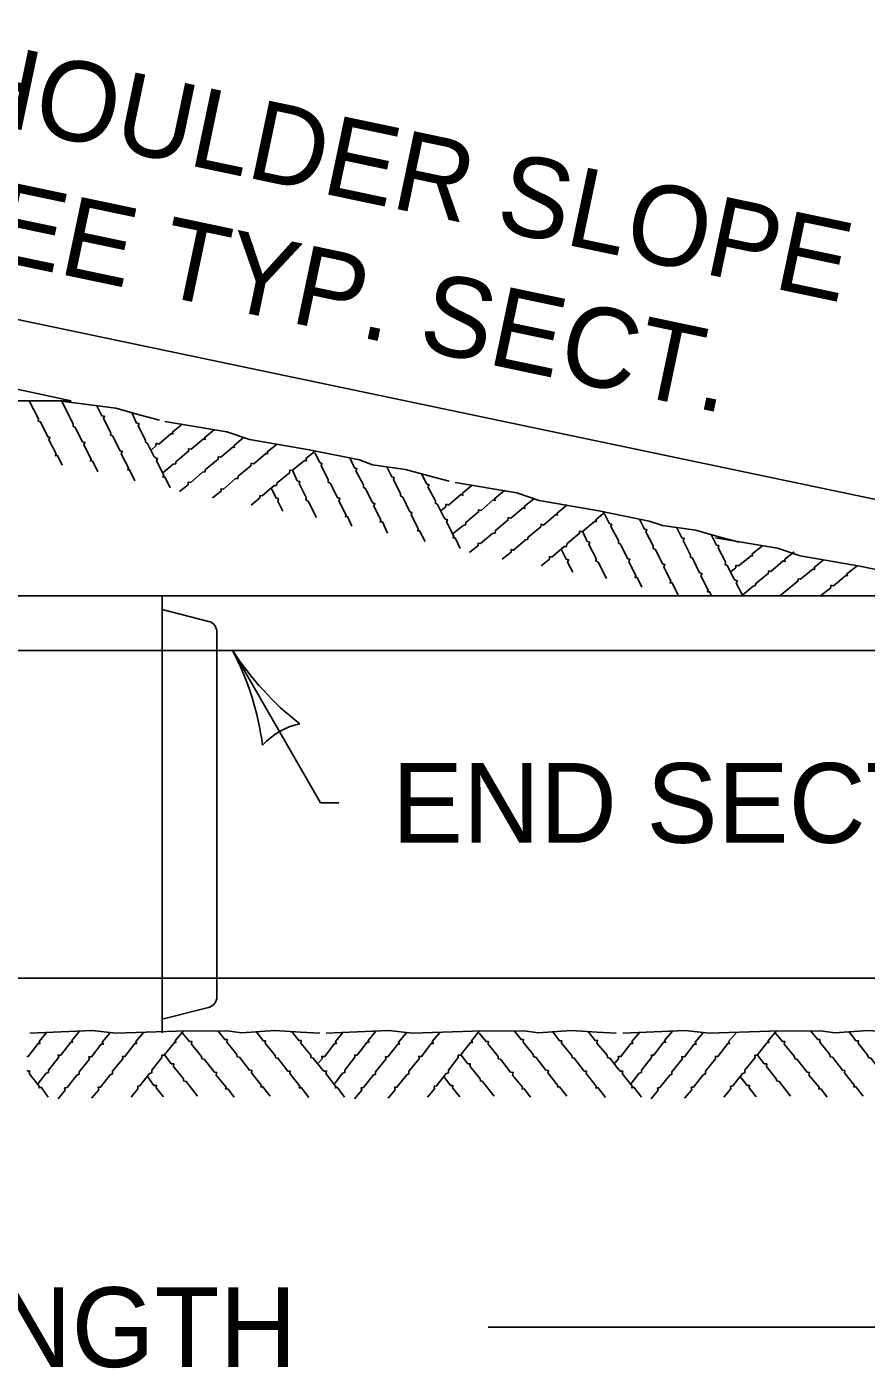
# Model space of a CAD drawing. Extents: x 49991.4 to 50022.1, y 49985 to 50011.4.
# Drawn here: x 50014.068 to 50014.7, y 49996.961 to 49997.97 of the extents above; entities that cross this region are included whole.
import ezdxf

# ---------------------------------------------------------------- set-up
doc = ezdxf.new("R2010")
doc.units = 0
for name, color, linetype in [('Level 1', 7, 'Continuous'), ('Level 2', 7, 'Continuous'), ('Level 3', 7, 'Continuous'), ('Level 4', 7, 'Continuous')]:
    doc.layers.add(name, color=color, linetype=linetype)

msp = doc.modelspace()

# ---------------------------------------------------------------- linework, layer by layer
at = {"layer": 'Level 1'}
for p, q in [((50013.8245, 49997.7486), (50014.1009, 49997.6892)), ((50014.1009, 49997.6892), (50012.6491, 49997.6892)), ((50012.6493, 49997.5423), (50014.7997, 49997.5423)), ((50014.1696, 49997.5423), (50014.1696, 49997.2136))]:
    msp.add_line(p, q, dxfattribs=at)
for points in [[(50014.0942, 49997.6406), (50014.0906, 49997.648), (50014.0891, 49997.6478), (50014.0897, 49997.6492), (50014.0843, 49997.6598), (50014.085, 49997.6616), (50014.0834, 49997.662), (50014.078, 49997.6732), (50014.0762, 49997.6739), (50014.0765, 49997.6756), (50014.0695, 49997.6892)], [(50014.0918, 49997.6892), (50014.1346, 49997.6835), (50014.1532, 49997.6784), (50014.1674, 49997.6745)], [(50014.121, 49997.6356), (50014.117, 49997.6439), (50014.1155, 49997.6439), (50014.116, 49997.6451), (50014.1106, 49997.6559), (50014.1114, 49997.6577), (50014.1096, 49997.6583), (50014.1041, 49997.6691), (50014.1024, 49997.67), (50014.1026, 49997.6718), (50014.0937, 49997.6892)], [(50014.149, 49997.629), (50014.145, 49997.6373), (50014.1436, 49997.6373), (50014.1442, 49997.6386), (50014.1386, 49997.6493), (50014.1395, 49997.651), (50014.1377, 49997.6516), (50014.1323, 49997.6626), (50014.1306, 49997.6634), (50014.1308, 49997.665), (50014.1254, 49997.6757), (50014.126, 49997.6775), (50014.1242, 49997.6778), (50014.1204, 49997.6853)], [(50014.1636, 49997.6469), (50014.1586, 49997.6571), (50014.1569, 49997.658), (50014.157, 49997.6596), (50014.1515, 49997.6703), (50014.1521, 49997.672), (50014.1503, 49997.6724), (50014.1466, 49997.6802)], [(50014.1846, 49997.6715), (50014.1773, 49997.6656), (50014.1776, 49997.6642), (50014.1761, 49997.6643), (50014.167, 49997.6566), (50014.166, 49997.6568)], [(50014.209, 49997.6674), (50014.2016, 49997.6616), (50014.202, 49997.66), (50014.2006, 49997.6604), (50014.1914, 49997.6526), (50014.1894, 49997.653), (50014.1894, 49997.6511), (50014.18, 49997.6434), (50014.1796, 49997.6416), (50014.1779, 49997.6415), (50014.1701, 49997.635)], [(50014.1716, 49997.6736), (50014.2181, 49997.6658), (50014.2352, 49997.6601), (50014.2802, 49997.6523), (50014.318, 49997.6446), (50014.328, 49997.641), (50014.3528, 49997.6374), (50014.3714, 49997.6325), (50014.3856, 49997.6286)], [(50014.1659, 49997.657), (50014.165, 49997.6571), (50014.1647, 49997.6553), (50014.1614, 49997.6523)], [(50014.2306, 49997.6612), (50014.2238, 49997.6556), (50014.2241, 49997.654), (50014.2229, 49997.6544), (50014.2136, 49997.6466), (50014.2118, 49997.647), (50014.2116, 49997.6451), (50014.2022, 49997.6374), (50014.2016, 49997.6356), (50014.2, 49997.6355), (50014.191, 49997.6277), (50014.1892, 49997.628), (50014.1892, 49997.626), (50014.1826, 49997.6208)], [(50014.256, 49997.6566), (50014.2486, 49997.6506), (50014.249, 49997.6492), (50014.2476, 49997.6494), (50014.2385, 49997.6416), (50014.2366, 49997.6421), (50014.2364, 49997.6403), (50014.2268, 49997.6325), (50014.2265, 49997.6307), (50014.2247, 49997.6306), (50014.2156, 49997.6226), (50014.2139, 49997.623), (50014.2139, 49997.6211), (50014.2073, 49997.616)], [(50014.1756, 49997.6236), (50014.1716, 49997.6319), (50014.1701, 49997.6316), (50014.1707, 49997.6331), (50014.1653, 49997.6439), (50014.166, 49997.6456), (50014.1644, 49997.6462), (50014.164, 49997.6469)], [(50014.285, 49997.6514), (50014.2776, 49997.6456), (50014.2781, 49997.6439), (50014.2766, 49997.6442), (50014.2674, 49997.6366), (50014.2656, 49997.637), (50014.2655, 49997.635), (50014.256, 49997.6274), (50014.2556, 49997.6254), (50014.2538, 49997.6253), (50014.2448, 49997.6176), (50014.243, 49997.6178), (50014.243, 49997.616), (50014.2366, 49997.6106)], [(50014.3124, 49997.5947), (50014.309, 49997.602), (50014.3075, 49997.6019), (50014.308, 49997.6031), (50014.3026, 49997.6139), (50014.3033, 49997.6157), (50014.3016, 49997.6163), (50014.2961, 49997.6271), (50014.2944, 49997.628), (50014.2946, 49997.6298), (50014.2892, 49997.6403), (50014.2898, 49997.642), (50014.2882, 49997.6426), (50014.2844, 49997.65)], [(50014.3393, 49997.5896), (50014.3354, 49997.598), (50014.3336, 49997.598), (50014.3342, 49997.5992), (50014.3288, 49997.61), (50014.3297, 49997.6118), (50014.3279, 49997.6124), (50014.3225, 49997.6232), (50014.321, 49997.624), (50014.321, 49997.6259), (50014.3154, 49997.6364), (50014.3162, 49997.638), (50014.3144, 49997.6386), (50014.3108, 49997.6462)], [(50014.2856, 49997.6013), (50014.2794, 49997.6136), (50014.2778, 49997.6145), (50014.278, 49997.6163), (50014.2726, 49997.6268), (50014.2732, 49997.6284), (50014.2712, 49997.629), (50014.2679, 49997.6364)], [(50014.3675, 49997.5832), (50014.3633, 49997.5914), (50014.3618, 49997.5914), (50014.3624, 49997.5926), (50014.357, 49997.6034), (50014.3576, 49997.605), (50014.356, 49997.6056), (50014.3506, 49997.6166), (50014.3489, 49997.6175), (50014.349, 49997.6192), (50014.3436, 49997.6298), (50014.3441, 49997.6314), (50014.3424, 49997.6319), (50014.3387, 49997.6394)], [(50014.3819, 49997.601), (50014.3768, 49997.6112), (50014.3752, 49997.612), (50014.3753, 49997.6139), (50014.3696, 49997.6244), (50014.3705, 49997.626), (50014.3686, 49997.6266), (50014.3648, 49997.6343)], [(50014.4029, 49997.6256), (50014.3956, 49997.6196), (50014.396, 49997.6181), (50014.3945, 49997.6186), (50014.3852, 49997.6106), (50014.3843, 49997.611)], [(50014.39, 49997.6277), (50014.4365, 49997.6199), (50014.4534, 49997.6142), (50014.4984, 49997.6064), (50014.5361, 49997.5986), (50014.5463, 49997.5952), (50014.571, 49997.5917), (50014.5896, 49997.5864), (50014.6039, 49997.5827)], [(50014.2604, 49997.6061), (50014.2565, 49997.6136), (50014.2571, 49997.6154), (50014.2553, 49997.616), (50014.2517, 49997.6235)], [(50014.4272, 49997.6216), (50014.42, 49997.6157), (50014.4203, 49997.6142), (50014.4188, 49997.6145), (50014.4096, 49997.6067), (50014.4077, 49997.6072), (50014.4077, 49997.6055), (50014.3981, 49997.5976), (50014.3978, 49997.5959), (50014.3962, 49997.5954), (50014.3886, 49997.5892)], [(50014.449, 49997.6151), (50014.4422, 49997.6097), (50014.4426, 49997.6082), (50014.4412, 49997.6085), (50014.432, 49997.6007), (50014.43, 49997.6012), (50014.4299, 49997.5992), (50014.4204, 49997.5916), (50014.4202, 49997.5896), (50014.4182, 49997.5894), (50014.4092, 49997.5818), (50014.4074, 49997.582), (50014.4074, 49997.5802), (50014.4008, 49997.5749)], [(50014.3842, 49997.611), (50014.3831, 49997.6112), (50014.3831, 49997.6094), (50014.3796, 49997.6066)], [(50014.4743, 49997.6106), (50014.4668, 49997.6046), (50014.4671, 49997.6031), (50014.4659, 49997.6036), (50014.4566, 49997.5956), (50014.4548, 49997.5962), (50014.4546, 49997.5944), (50014.445, 49997.5864), (50014.4446, 49997.5848), (50014.443, 49997.5846), (50014.434, 49997.5767), (50014.4322, 49997.5772), (50014.4322, 49997.5752), (50014.4256, 49997.57)], [(50014.5031, 49997.6055), (50014.496, 49997.5996), (50014.4965, 49997.5982), (50014.495, 49997.5983), (50014.4857, 49997.5906), (50014.4839, 49997.591), (50014.4836, 49997.5892), (50014.4743, 49997.5815), (50014.474, 49997.5796), (50014.4722, 49997.5794), (50014.463, 49997.5716), (50014.4611, 49997.5719), (50014.4611, 49997.57), (50014.4548, 49997.565)], [(50014.5307, 49997.5488), (50014.5271, 49997.5562), (50014.5256, 49997.5562), (50014.5262, 49997.5575), (50014.5208, 49997.5682), (50014.5217, 49997.5698), (50014.5199, 49997.5704), (50014.5145, 49997.5812), (50014.513, 49997.5821), (50014.513, 49997.5839), (50014.5074, 49997.5946), (50014.508, 49997.5962), (50014.5064, 49997.5966), (50014.5026, 49997.6042)], [(50014.3939, 49997.5779), (50014.39, 49997.586), (50014.3885, 49997.586), (50014.389, 49997.5872), (50014.3836, 49997.598), (50014.3843, 49997.5996), (50014.3826, 49997.6001), (50014.3822, 49997.601)], [(50014.5583, 49997.5423), (50014.5536, 49997.5521), (50014.552, 49997.5521), (50014.5524, 49997.5533), (50014.5472, 49997.5641), (50014.548, 49997.5659), (50014.5462, 49997.5665), (50014.5409, 49997.5773), (50014.5391, 49997.578), (50014.5391, 49997.58), (50014.5337, 49997.5905), (50014.5344, 49997.5923), (50014.5326, 49997.5926), (50014.529, 49997.6001)], [(50014.504, 49997.5554), (50014.4977, 49997.5677), (50014.496, 49997.5686), (50014.4962, 49997.5704), (50014.4908, 49997.581), (50014.4914, 49997.5827), (50014.4896, 49997.5832), (50014.4862, 49997.5905)], [(50014.5832, 49997.5423), (50014.5817, 49997.5455), (50014.58, 49997.5455), (50014.5806, 49997.5467), (50014.5751, 49997.5575), (50014.576, 49997.5593), (50014.5742, 49997.5596), (50014.5688, 49997.5707), (50014.5673, 49997.5714), (50014.5673, 49997.5731), (50014.5619, 49997.5839), (50014.5626, 49997.5856), (50014.5607, 49997.586), (50014.5571, 49997.5935)], [(50014.6002, 49997.555), (50014.595, 49997.5653), (50014.5934, 49997.566), (50014.5936, 49997.568), (50014.5882, 49997.5785), (50014.5886, 49997.5802), (50014.5868, 49997.5806), (50014.583, 49997.5886)], [(50014.5862, 49997.5861), (50014.6327, 49997.5783), (50014.6498, 49997.5726), (50014.6948, 49997.5648), (50014.7326, 49997.557), (50014.7427, 49997.5534), (50014.7674, 49997.5501), (50014.786, 49997.5449), (50014.8003, 49997.5411)], [(50014.4786, 49997.5602), (50014.4746, 49997.5677), (50014.4755, 49997.5695), (50014.4736, 49997.57), (50014.47, 49997.5774)], [(50014.6212, 49997.5797), (50014.6138, 49997.574), (50014.6141, 49997.5725), (50014.6129, 49997.5726), (50014.6034, 49997.565), (50014.6026, 49997.5652)], [(50014.6454, 49997.5756), (50014.6381, 49997.5698), (50014.6386, 49997.5683), (50014.6372, 49997.5686), (50014.6279, 49997.5608), (50014.626, 49997.5611), (50014.626, 49997.5594), (50014.6165, 49997.5516), (50014.616, 49997.55), (50014.6144, 49997.5496), (50014.6066, 49997.5431)], [(50014.6024, 49997.5652), (50014.6015, 49997.5653), (50014.6015, 49997.5635), (50014.5979, 49997.5606)], [(50014.6672, 49997.5692), (50014.6604, 49997.5638), (50014.6609, 49997.5623), (50014.6594, 49997.5624), (50014.6501, 49997.5548), (50014.6483, 49997.5551), (50014.6482, 49997.5534), (50014.6347, 49997.5423)], [(50014.6926, 49997.5647), (50014.685, 49997.559), (50014.6855, 49997.5575), (50014.6842, 49997.5576), (50014.675, 49997.55), (50014.673, 49997.5503), (50014.6729, 49997.5485), (50014.6653, 49997.5423)], [(50014.6067, 49997.5423), (50014.6018, 49997.552), (50014.6026, 49997.5536), (50014.6009, 49997.5542), (50014.6004, 49997.555)], [(50014.0828, 49997.2141), (50014.0768, 49997.207), (50014.0775, 49997.2055), (50014.0761, 49997.2055), (50014.0685, 49997.1959), (50014.0677, 49997.1959)], [(50014.0699, 49997.2135), (50014.1169, 49997.2154), (50014.1347, 49997.2133), (50014.1803, 49997.2148), (50014.2187, 49997.2151), (50014.2293, 49997.2136), (50014.2544, 49997.2154), (50014.2737, 49997.2142), (50014.2883, 49997.2135)], [(50014.1074, 49997.2149), (50014.1014, 49997.2079), (50014.1021, 49997.2065), (50014.1007, 49997.2065), (50014.0933, 49997.1969), (50014.0912, 49997.1969), (50014.0917, 49997.1953), (50014.0839, 49997.1855), (50014.0839, 49997.1839), (50014.0822, 49997.1833), (50014.0762, 49997.1755)], [(50014.1301, 49997.2133), (50014.1243, 49997.2065), (50014.1253, 49997.2052), (50014.1237, 49997.2052), (50014.1164, 49997.1956), (50014.1143, 49997.1956), (50014.1147, 49997.1939), (50014.1069, 49997.1842), (50014.1069, 49997.1825), (50014.1053, 49997.1818), (50014.0979, 49997.1725), (50014.0961, 49997.1722), (50014.0965, 49997.1705), (50014.0912, 49997.1639)], [(50014.1557, 49997.2141), (50014.1497, 49997.207), (50014.1503, 49997.2055), (50014.1489, 49997.2055), (50014.1415, 49997.1959), (50014.1397, 49997.1959), (50014.1398, 49997.1941), (50014.1321, 49997.1847), (50014.1321, 49997.1827), (50014.1303, 49997.1821), (50014.1231, 49997.1727), (50014.1213, 49997.1727), (50014.1218, 49997.1707), (50014.1164, 49997.1644)], [(50014.1853, 49997.2149), (50014.1794, 49997.2076), (50014.1799, 49997.2064), (50014.1787, 49997.2064), (50014.1711, 49997.1968), (50014.1692, 49997.1968), (50014.1693, 49997.1951), (50014.1617, 49997.1855), (50014.1617, 49997.1836), (50014.1601, 49997.1831), (50014.1527, 49997.1737), (50014.1511, 49997.1735), (50014.1512, 49997.1716), (50014.1463, 49997.1653)], [(50014.2238, 49997.1653), (50014.2189, 49997.1716), (50014.2173, 49997.1713), (50014.2177, 49997.1727), (50014.2101, 49997.1819), (50014.2105, 49997.1839), (50014.2088, 49997.1841), (50014.2011, 49997.1937), (50014.1993, 49997.1941), (50014.1992, 49997.1959), (50014.1915, 49997.2051), (50014.1919, 49997.207), (50014.1901, 49997.207), (50014.1849, 49997.2135)], [(50014.2509, 49997.1659), (50014.2454, 49997.1731), (50014.2439, 49997.1728), (50014.2442, 49997.1741), (50014.2367, 49997.1835), (50014.2371, 49997.1854), (50014.2352, 49997.1855), (50014.2277, 49997.1953), (50014.2261, 49997.1956), (50014.2257, 49997.1974), (50014.2183, 49997.2065), (50014.2185, 49997.2085), (50014.2167, 49997.2085), (50014.2117, 49997.2149)], [(50014.2799, 49997.1651), (50014.2742, 49997.1725), (50014.2727, 49997.1721), (50014.2731, 49997.1734), (50014.2657, 49997.183), (50014.2659, 49997.1847), (50014.2641, 49997.1849), (50014.2567, 49997.1945), (50014.2549, 49997.195), (50014.2545, 49997.1967), (50014.2471, 49997.2059), (50014.2473, 49997.2076), (50014.2455, 49997.2076), (50014.2405, 49997.2145)], [(50014.2904, 49997.1855), (50014.2832, 49997.1945), (50014.2815, 49997.1951), (50014.2814, 49997.1968), (50014.2739, 49997.2059), (50014.2741, 49997.2079), (50014.2723, 49997.2079), (50014.2669, 49997.2148)], [(50014.3059, 49997.2141), (50014.2999, 49997.207), (50014.3007, 49997.2055), (50014.2993, 49997.2055), (50014.2919, 49997.1959), (50014.2907, 49997.1959)], [(50014.2929, 49997.2135), (50014.3401, 49997.2154), (50014.3579, 49997.2133), (50014.4033, 49997.2148), (50014.4421, 49997.2151), (50014.4525, 49997.2136), (50014.4777, 49997.2154), (50014.4968, 49997.2142), (50014.5113, 49997.2135)], [(50014.3305, 49997.2149), (50014.3247, 49997.2079), (50014.3253, 49997.2065), (50014.3239, 49997.2065), (50014.3163, 49997.1969), (50014.3145, 49997.1969), (50014.3147, 49997.1953), (50014.3071, 49997.1855), (50014.3071, 49997.1839), (50014.3054, 49997.1833), (50014.2994, 49997.1755)], [(50014.3533, 49997.2133), (50014.3475, 49997.2065), (50014.3483, 49997.2052), (50014.3469, 49997.2052), (50014.3395, 49997.1956), (50014.3377, 49997.1956), (50014.3378, 49997.1939), (50014.3301, 49997.1842), (50014.3301, 49997.1825), (50014.3283, 49997.1818), (50014.3211, 49997.1725), (50014.3193, 49997.1722), (50014.3198, 49997.1705), (50014.3144, 49997.1639)], [(50014.3789, 49997.2141), (50014.3729, 49997.207), (50014.3737, 49997.2055), (50014.3721, 49997.2055), (50014.3648, 49997.1959), (50014.3627, 49997.1959), (50014.3631, 49997.1941), (50014.3553, 49997.1847), (50014.3553, 49997.1827), (50014.3537, 49997.1821), (50014.3463, 49997.1727), (50014.3445, 49997.1727), (50014.3449, 49997.1707), (50014.3397, 49997.1644)], [(50014.4083, 49997.2149), (50014.4025, 49997.2076), (50014.4032, 49997.2064), (50014.4017, 49997.2064), (50014.3942, 49997.1968), (50014.3924, 49997.1968), (50014.3925, 49997.1951), (50014.3851, 49997.1855), (50014.3851, 49997.1836), (50014.3834, 49997.1831), (50014.3761, 49997.1737), (50014.3743, 49997.1735), (50014.3745, 49997.1716), (50014.3693, 49997.1653)], [(50014.4469, 49997.1653), (50014.4421, 49997.1716), (50014.4405, 49997.1713), (50014.4409, 49997.1727), (50014.4332, 49997.1819), (50014.4338, 49997.1839), (50014.4319, 49997.1841), (50014.4243, 49997.1937), (50014.4225, 49997.1941), (50014.4224, 49997.1959), (50014.4149, 49997.2051), (50014.4151, 49997.207), (50014.4134, 49997.207), (50014.4081, 49997.2135)], [(50014.4741, 49997.1659), (50014.4687, 49997.1731), (50014.4673, 49997.1728), (50014.4674, 49997.1741), (50014.4599, 49997.1835), (50014.4603, 49997.1854), (50014.4585, 49997.1855), (50014.4509, 49997.1953), (50014.4493, 49997.1956), (50014.4489, 49997.1974), (50014.4413, 49997.2065), (50014.4417, 49997.2085), (50014.4398, 49997.2085), (50014.4347, 49997.2149)], [(50014.5033, 49997.1651), (50014.4975, 49997.1725), (50014.4961, 49997.1721), (50014.4962, 49997.1734), (50014.4887, 49997.183), (50014.4891, 49997.1847), (50014.4873, 49997.1849), (50014.4797, 49997.1945), (50014.4781, 49997.195), (50014.4779, 49997.1967), (50014.4703, 49997.2059), (50014.4705, 49997.2076), (50014.4687, 49997.2076), (50014.4637, 49997.2145)], [(50014.5137, 49997.1855), (50014.5065, 49997.1945), (50014.5047, 49997.1951), (50014.5045, 49997.1968), (50014.4969, 49997.2059), (50014.4973, 49997.2079), (50014.4955, 49997.2079), (50014.4901, 49997.2148)], [(50014.5292, 49997.2141), (50014.5232, 49997.207), (50014.5238, 49997.2055), (50014.5225, 49997.2055), (50014.5149, 49997.1959), (50014.5141, 49997.1959)], [(50014.5163, 49997.2135), (50014.5634, 49997.2154), (50014.5813, 49997.2133), (50014.6267, 49997.2148), (50014.6653, 49997.2151), (50014.6759, 49997.2136), (50014.7008, 49997.2154), (50014.7201, 49997.2142), (50014.7347, 49997.2135)], [(50014.5538, 49997.2149), (50014.5478, 49997.2079), (50014.5485, 49997.2065), (50014.5471, 49997.2065), (50014.5397, 49997.1969), (50014.5377, 49997.1969), (50014.5381, 49997.1953), (50014.5304, 49997.1855), (50014.5304, 49997.1839), (50014.5287, 49997.1833), (50014.5227, 49997.1755)], [(50014.5765, 49997.2133), (50014.5709, 49997.2065), (50014.5717, 49997.2052), (50014.5701, 49997.2052), (50014.5627, 49997.1956), (50014.5607, 49997.1956), (50014.5611, 49997.1939), (50014.5533, 49997.1842), (50014.5533, 49997.1825), (50014.5517, 49997.1818), (50014.5443, 49997.1725), (50014.5425, 49997.1722), (50014.5429, 49997.1705), (50014.5377, 49997.1639)], [(50014.6023, 49997.2141), (50014.5959, 49997.207), (50014.5967, 49997.2055), (50014.5953, 49997.2055), (50014.5879, 49997.1959), (50014.5861, 49997.1959), (50014.5862, 49997.1941), (50014.5785, 49997.1847), (50014.5785, 49997.1827), (50014.5769, 49997.1821), (50014.5695, 49997.1727), (50014.5679, 49997.1727), (50014.5682, 49997.1707), (50014.5628, 49997.1644)], [(50014.6317, 49997.2149), (50014.6257, 49997.2076), (50014.6264, 49997.2064), (50014.6251, 49997.2064), (50014.6175, 49997.1968), (50014.6157, 49997.1968), (50014.6159, 49997.1951), (50014.6083, 49997.1855), (50014.6083, 49997.1836), (50014.6065, 49997.1831), (50014.5993, 49997.1737), (50014.5975, 49997.1735), (50014.5977, 49997.1716), (50014.5923, 49997.1653)], [(50014.6701, 49997.1653), (50014.6654, 49997.1716), (50014.6639, 49997.1713), (50014.6641, 49997.1727), (50014.6565, 49997.1819), (50014.6569, 49997.1839), (50014.6551, 49997.1841), (50014.6475, 49997.1937), (50014.6459, 49997.1941), (50014.6455, 49997.1959), (50014.6379, 49997.2051), (50014.6384, 49997.207), (50014.6365, 49997.207), (50014.6313, 49997.2135)], [(50014.6973, 49997.1659), (50014.6918, 49997.1731), (50014.6903, 49997.1728), (50014.6907, 49997.1741), (50014.6833, 49997.1835), (50014.6835, 49997.1854), (50014.6817, 49997.1855), (50014.6743, 49997.1953), (50014.6725, 49997.1956), (50014.6721, 49997.1974), (50014.6647, 49997.2065), (50014.6648, 49997.2085), (50014.6631, 49997.2085), (50014.6579, 49997.2149)], [(50014.7263, 49997.1651), (50014.7207, 49997.1725), (50014.7193, 49997.1721), (50014.7195, 49997.1734), (50014.7119, 49997.183), (50014.7123, 49997.1847), (50014.7105, 49997.1849), (50014.7031, 49997.1945), (50014.7013, 49997.195), (50014.7009, 49997.1967), (50014.6935, 49997.2059), (50014.6939, 49997.2076), (50014.6919, 49997.2076), (50014.6867, 49997.2145)], [(50014.1961, 49997.1661), (50014.1877, 49997.1771), (50014.1857, 49997.1775), (50014.1855, 49997.1791), (50014.1781, 49997.1884), (50014.1782, 49997.1902), (50014.1764, 49997.1902), (50014.1715, 49997.1968)], [(50014.2905, 49997.1959), (50014.2897, 49997.1959), (50014.2899, 49997.1941), (50014.2869, 49997.1907)], [(50014.4194, 49997.1661), (50014.4107, 49997.1771), (50014.4091, 49997.1775), (50014.4089, 49997.1791), (50014.4013, 49997.1884), (50014.4015, 49997.1902), (50014.3997, 49997.1902), (50014.3947, 49997.1968)], [(50014.5139, 49997.1959), (50014.5129, 49997.1959), (50014.5131, 49997.1941), (50014.5103, 49997.1907)], [(50014.6425, 49997.1661), (50014.6341, 49997.1771), (50014.6323, 49997.1775), (50014.6319, 49997.1791), (50014.6245, 49997.1884), (50014.6247, 49997.1902), (50014.6228, 49997.1902), (50014.6177, 49997.1968)], [(50014.0837, 49997.1653), (50014.0783, 49997.1727), (50014.0768, 49997.1722), (50014.0769, 49997.1735), (50014.0695, 49997.183), (50014.0699, 49997.1848), (50014.0683, 49997.1849), (50014.0677, 49997.1855)], [(50014.1704, 49997.1656), (50014.1651, 49997.1722), (50014.1653, 49997.1741), (50014.1633, 49997.1741), (50014.1584, 49997.1809)], [(50014.3069, 49997.1653), (50014.3013, 49997.1727), (50014.2999, 49997.1722), (50014.3001, 49997.1735), (50014.2927, 49997.183), (50014.2933, 49997.1848), (50014.2913, 49997.1849), (50014.2907, 49997.1855)], [(50014.3937, 49997.1656), (50014.3882, 49997.1722), (50014.3883, 49997.1741), (50014.3867, 49997.1741), (50014.3815, 49997.1809)], [(50014.5303, 49997.1653), (50014.5247, 49997.1727), (50014.5231, 49997.1722), (50014.5233, 49997.1735), (50014.5159, 49997.183), (50014.5163, 49997.1848), (50014.5143, 49997.1849), (50014.5141, 49997.1855)], [(50014.6168, 49997.1656), (50014.6114, 49997.1722), (50014.6117, 49997.1741), (50014.6099, 49997.1741), (50014.6048, 49997.1809)]]:
    msp.add_lwpolyline(points, dxfattribs=at)
at = {"layer": 'Level 3'}
for p, q in [((50013.8318, 49997.7982), (50014.8104, 49997.5931)), ((50014.2888, 49997.3866), (50014.2226, 49997.5013)), ((50014.3025, 49997.3866), (50014.2888, 49997.3866)), ((50015.1696, 49996.9922), (50014.415, 49996.9922))]:
    msp.add_line(p, q, dxfattribs=at)
for centre, radius, start, end in [((50014.0335, 49997.4023), 0.2134, 7.4403, 27.6238), ((50014.4106, 49997.6225), 0.2237, 212.8116, 232.0615), ((50014.2841, 49997.3947), 0.0526, 102.1231, 137.8455)]:
    msp.add_arc(centre, radius, start, end, dxfattribs=at)
at = {"layer": 'Level 4'}
for p, q in [((50014.1696, 49997.532), (50014.2045, 49997.5232)), ((50014.2107, 49997.5152), (50014.2107, 49997.2408)), ((50012.6493, 49997.5013), (50014.8057, 49997.5013)), ((50012.6493, 49997.2547), (50015.1696, 49997.2547)), ((50014.1696, 49997.224), (50014.2045, 49997.2327))]:
    msp.add_line(p, q, dxfattribs=at)
for centre, start, end in [((50014.2025, 49997.5152), 0, 75.8703), ((50014.2025, 49997.2407), 284.1107, 0)]:
    msp.add_arc(centre, 0.00822, start, end, dxfattribs=at)

# ---------------------------------------------------------------- texts
at = {"layer": 'Level 2'}
for s, p in [('SHOULDER SLOPE', (50013.9609, 49997.9144)), ('SEE TYP. SECT.', (50013.9855, 49997.807))]:
    msp.add_text(s, height=0.06, rotation=348.1237, dxfattribs=at).set_placement(p)
for s, p in [('END SECTION', (50014.3425, 49997.3566)), ('PLANNED CULVERT LENGTH', (50013.1472, 49996.9622))]:
    msp.add_text(s, height=0.06, dxfattribs=at).set_placement(p)

doc.saveas('drawing.dxf')
